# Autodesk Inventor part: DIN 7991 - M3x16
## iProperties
Created: 2007-03
Part Number: DIN 7991 - M3x16
Material: Steel, Mild
Description: Hexagon socket countersunk head cap screws
Document SubType Name: Modeling
Standard: DIN 7991
Designer: Andy Moles
Standards Organization: DIN
Language: en-US
Size Designation: M3x8
Categories: <MemberInstance Version="R10.0.0"><Categories><Category DisplayName="Fasteners" InternalName="e4da775c-781d-43d5-af7c-5136215cf5a6" Mnemonic="FSTN"><Category Di
Density: 7.86 g/cm^3
Author: Andy Moles
Revision Number: 1
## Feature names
1. Revolution1
2. Extrusion1
3. Fillet1
4. Chamfer1
